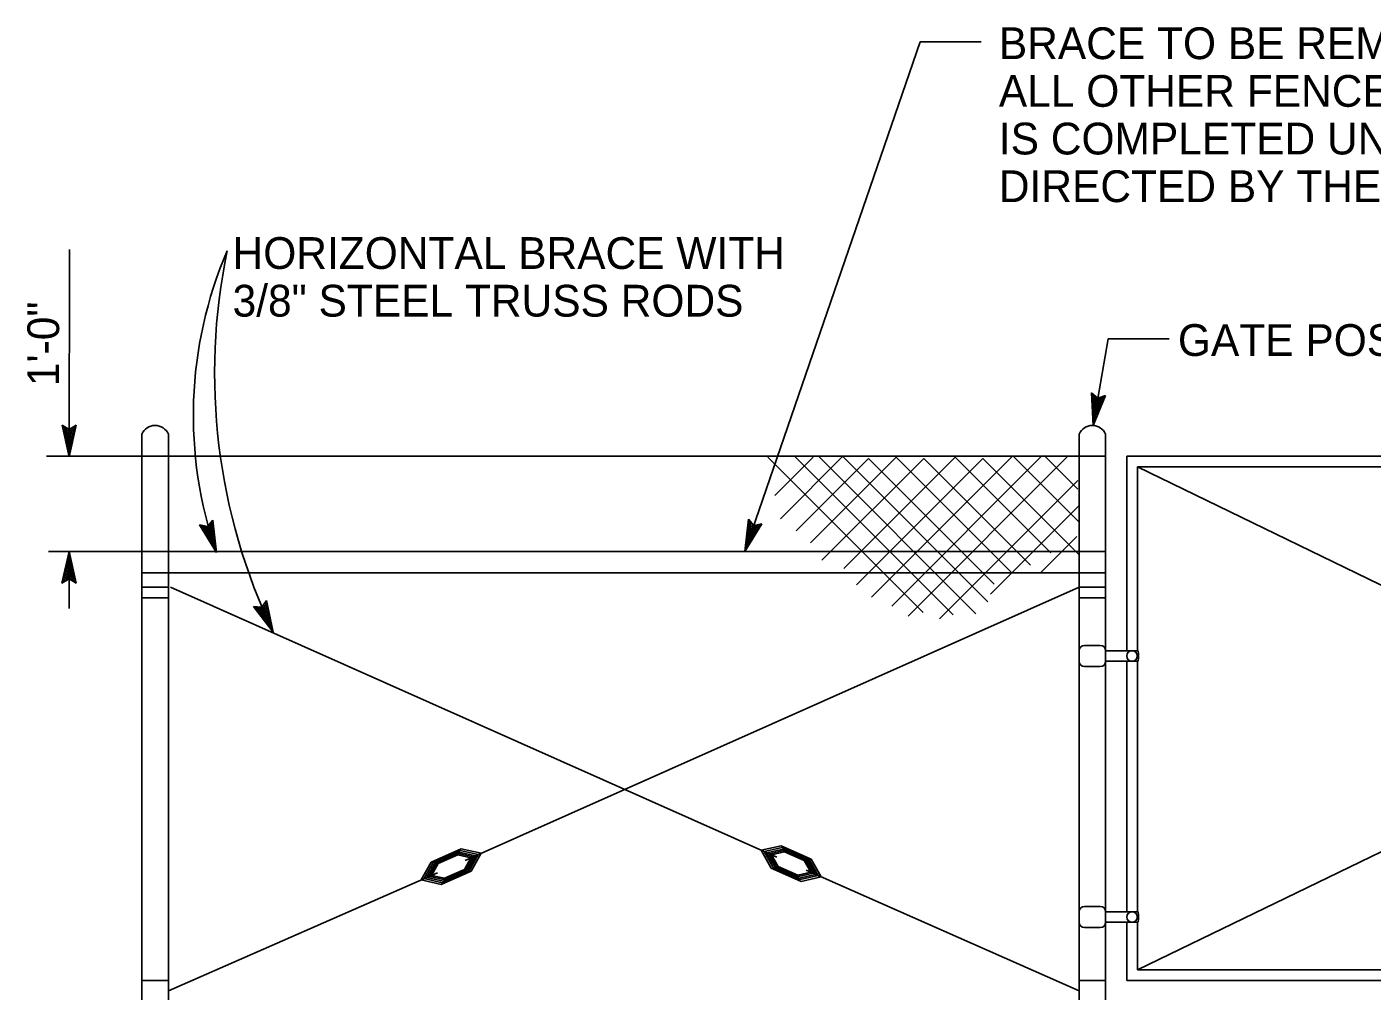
# Model space of a CAD drawing. Extents: x -121875 to -117742, y -103854 to -101122.
# Drawn here: x -121365.7 to -121111.6, y -102377.2 to -102195.2 of the extents above; entities that cross this region are included whole.
import ezdxf

# ---------------------------------------------------------------- set-up
doc = ezdxf.new("R2010")
doc.units = 0
for name, color, linetype in [('G-MARK', 7, 'Continuous'), ('G-TEXT', 7, 'Continuous'), ('Misc CnstDet(22)', 7, 'Continuous'), ('Nongeo Data(60)', 7, 'Continuous')]:
    doc.layers.add(name, color=color, linetype=linetype)

msp = doc.modelspace()

# ---------------------------------------------------------------- linework, layer by layer
at = {"layer": 'G-MARK'}
for p, q in [((-121197, -102197.99), (-121185.5, -102197.99)), ((-121357.66, -102237.2), (-121357.7, -102276.37)), ((-121161.49, -102254.04), (-121149.99, -102254.04)), ((-121164.33, -102270.41), (-121164.62, -102264.27)), ((-121164.62, -102264.27), (-121164.62, -102264.27)), ((-121164.62, -102264.27), (-121163.44, -102265.29)), ((-121161.99, -102264.73), (-121164.33, -102270.41)), ((-121164.1, -102269.04), (-121164.3, -102264.56)), ((-121163.86, -102267.69), (-121163.99, -102264.8)), ((-121163.44, -102265.29), (-121161.99, -102264.73)), ((-121161.99, -102264.73), (-121161.99, -102264.73)), ((-121162.37, -102264.88), (-121164.1, -102269.05)), ((-121162.77, -102265.05), (-121163.86, -102267.69)), ((-121163.62, -102266.33), (-121163.68, -102265.09)), ((-121163.14, -102265.16), (-121163.62, -102266.33)), ((-121164.33, -102270.41), (-121164.33, -102270.41)), ((-121230.1, -102294.24), (-121229.41, -102288.14)), ((-121226.89, -102289.01), (-121230.1, -102294.24)), ((-121229.66, -102292.93), (-121229.15, -102288.48)), ((-121227.29, -102289.09), (-121229.66, -102292.94)), ((-121229.41, -102288.14), (-121229.41, -102288.14)), ((-121229.41, -102288.14), (-121228.41, -102289.33)), ((-121229.2, -102291.63), (-121228.88, -102288.76)), ((-121227.71, -102289.2), (-121229.2, -102291.63)), ((-121228.75, -102290.33), (-121228.61, -102289.1)), ((-121228.09, -102289.25), (-121228.75, -102290.33)), ((-121228.41, -102289.33), (-121226.89, -102289.01)), ((-121226.89, -102289.01), (-121226.89, -102289.01)), ((-121357.72, -102294.19), (-121357.73, -102304.97)), ((-121230.1, -102294.24), (-121230.1, -102294.24))]:
    msp.add_line(p, q, dxfattribs=at)
for points in [[(-121230.1, -102294.24), (-121197, -102197.99), (-121197, -102197.99)], [(-121164.33, -102270.41), (-121161.49, -102254.04)]]:
    msp.add_lwpolyline(points, dxfattribs=at)
for centre, radius, start, end in [((-121255.69, -102268.51), 78.56, 156.7153, 199.2421), ((-121216.67, -102260.54), 113.56, 168.2679, 205.5228)]:
    msp.add_arc(centre, radius, start, end, dxfattribs=at)
at = {"layer": 'G-TEXT'}
for p, q in [((-121357.7, -102276.37), (-121359.02, -102270.37)), ((-121359.02, -102270.37), (-121359.02, -102270.37)), ((-121359.02, -102270.37), (-121357.69, -102271.17)), ((-121357.7, -102274.98), (-121358.67, -102270.61)), ((-121357.69, -102273.61), (-121358.32, -102270.79)), ((-121357.69, -102272.23), (-121357.96, -102271.02)), ((-121356.35, -102270.38), (-121357.7, -102276.37)), ((-121356.71, -102270.59), (-121357.7, -102274.99)), ((-121357.69, -102271.17), (-121356.35, -102270.38)), ((-121357.07, -102270.83), (-121357.69, -102273.61)), ((-121357.42, -102271), (-121357.69, -102272.23)), ((-121356.35, -102270.38), (-121356.35, -102270.38)), ((-121357.7, -102276.37), (-121357.7, -102276.37)), ((-121329.87, -102294.4), (-121333.07, -102289.16)), ((-121333.07, -102289.16), (-121333.07, -102289.16)), ((-121333.07, -102289.16), (-121331.56, -102289.48)), ((-121330.32, -102293.09), (-121332.66, -102289.26)), ((-121330.76, -102291.79), (-121332.27, -102289.32)), ((-121331.21, -102290.48), (-121331.86, -102289.42)), ((-121331.56, -102289.48), (-121330.55, -102288.29)), ((-121331.35, -102289.23), (-121331.21, -102290.48)), ((-121331.08, -102288.95), (-121330.76, -102291.79)), ((-121330.82, -102288.61), (-121330.31, -102293.09)), ((-121330.55, -102288.29), (-121330.55, -102288.29)), ((-121330.55, -102288.29), (-121329.87, -102294.4)), ((-121359.06, -102300.19), (-121357.72, -102294.19)), ((-121357.72, -102294.19), (-121357.72, -102294.19)), ((-121357.72, -102294.19), (-121356.39, -102300.19)), ((-121329.87, -102294.4), (-121329.87, -102294.4)), ((-121358.71, -102299.97), (-121357.72, -102295.57)), ((-121358.35, -102299.74), (-121357.72, -102296.95)), ((-121357.72, -102295.58), (-121356.75, -102299.95)), ((-121357.72, -102296.95), (-121357.1, -102299.78)), ((-121357.72, -102299.39), (-121359.06, -102300.19)), ((-121359.06, -102300.19), (-121359.06, -102300.19)), ((-121358, -102299.56), (-121357.73, -102298.33)), ((-121357.73, -102298.33), (-121357.46, -102299.54)), ((-121356.39, -102300.19), (-121357.72, -102299.39)), ((-121356.39, -102300.19), (-121356.39, -102300.19)), ((-121319.15, -102309.47), (-121322.88, -102304.59)), ((-121322.88, -102304.59), (-121322.88, -102304.59)), ((-121322.88, -102304.59), (-121321.34, -102304.76)), ((-121319.74, -102308.21), (-121322.45, -102304.65)), ((-121320.31, -102306.97), (-121322.06, -102304.67)), ((-121320.89, -102305.71), (-121321.64, -102304.73)), ((-121321.34, -102304.76), (-121320.46, -102303.47)), ((-121321.16, -102304.48), (-121320.89, -102305.71)), ((-121320.92, -102304.18), (-121320.31, -102306.97)), ((-121320.69, -102303.81), (-121319.73, -102308.22)), ((-121320.46, -102303.47), (-121320.46, -102303.47)), ((-121320.46, -102303.47), (-121319.15, -102309.47)), ((-121319.15, -102309.47), (-121319.15, -102309.47))]:
    msp.add_line(p, q, dxfattribs=at)
at = {"layer": 'Nongeo Data(60)'}
for p, q in [((-121343.97, -102426.24), (-121343.97, -102272.05)), ((-121338.97, -102426.24), (-121338.97, -102272.05)), ((-121166.97, -102358.97), (-121166.97, -102272.05)), ((-121161.97, -102358.97), (-121161.97, -102272.05)), ((-121343.8, -102276.24), (-121361.96, -102276.24)), ((-121343.97, -102426.24), (-121343.97, -102276.24)), ((-121161.97, -102276.24), (-121343.8, -102276.24)), ((-121196.43, -102305.72), (-121225.74, -102276.41)), ((-121224.43, -102283.65), (-121217.2, -102276.41)), ((-121223.37, -102288.04), (-121211.5, -102276.17)), ((-121190.73, -102306.2), (-121220.76, -102276.17)), ((-121220.4, -102290.29), (-121206.75, -102276.65)), ((-121217.67, -102292.55), (-121201.53, -102276.41)), ((-121186.46, -102305.96), (-121216.25, -102276.17)), ((-121215.53, -102295.87), (-121196.31, -102276.65)), ((-121184.21, -102303.7), (-121211.74, -102276.17)), ((-121211.38, -102297.41), (-121190.38, -102276.41)), ((-121209.01, -102300.5), (-121185.16, -102276.65)), ((-121183.02, -102300.38), (-121206.75, -102276.65)), ((-121206.16, -102302.87), (-121179.46, -102276.17)), ((-121202.34, -102304.51), (-121174.01, -102276.18)), ((-121179.82, -102298.13), (-121201.53, -102276.41)), ((-121199.28, -102306.43), (-121169.02, -102276.17)), ((-121176.14, -102296.82), (-121196.31, -102276.65)), ((-121172.34, -102294.45), (-121190.38, -102276.41)), ((-121167, -102294.8), (-121185.16, -102276.65)), ((-121167, -102288.63), (-121179.46, -102276.17)), ((-121167.2, -102282.47), (-121173.6, -102276.07)), ((-121157.97, -102312.97), (-121157.97, -102276.24)), ((-120957.97, -102276.24), (-121157.97, -102276.24)), ((-121155.97, -102312.95), (-121155.97, -102278.24)), ((-121155.97, -102278.24), (-121019.1, -102344.59)), ((-120959.97, -102278.24), (-121155.97, -102278.24)), ((-121193.34, -102306.91), (-121167.21, -102280.78)), ((-121183.73, -102302.28), (-121166.96, -102285.51)), ((-121174.12, -102298.13), (-121167.41, -102291.41)), ((-121361.58, -102294.23), (-121340.98, -102294.23)), ((-121161.97, -102294.24), (-121343.97, -102294.24)), ((-121161.97, -102298.24), (-121343.97, -102298.24)), ((-121338.97, -102300.95), (-121343.97, -102300.95)), ((-121338.97, -102302.95), (-121343.97, -102302.95)), ((-121338.57, -102300.95), (-121224.03, -102351.93)), ((-121166.97, -102300.95), (-121282.92, -102352.55)), ((-121161.97, -102300.95), (-121166.97, -102300.95)), ((-121161.97, -102302.95), (-121166.97, -102302.95)), ((-121166.97, -102311.94), (-121166.97, -102309.67)), ((-121161.97, -102311.93), (-121161.97, -102309.67)), ((-121157.97, -102312.95), (-121157.97, -102309.67)), ((-121166.97, -102317.59), (-121166.97, -102311.9)), ((-121166.97, -102314.95), (-121166.97, -102312.95)), ((-121162.97, -102311.95), (-121165.97, -102311.95)), ((-121161.97, -102317.59), (-121161.97, -102311.93)), ((-121155.85, -102312.95), (-121161.97, -102312.95)), ((-121161.97, -102314.95), (-121161.97, -102312.95)), ((-121155.85, -102314.95), (-121161.97, -102314.95)), ((-121157.97, -102358.97), (-121157.97, -102314.81)), ((-121157.97, -102317.59), (-121157.97, -102314.95)), ((-121155.97, -102362.24), (-121155.97, -102314.95)), ((-121162.97, -102315.95), (-121165.97, -102315.95)), ((-121100.56, -102346.39), (-121155.97, -102373.24)), ((-121283.68, -102350.35), (-121289.34, -102352.87)), ((-121283.86, -102350.69), (-121288.96, -102352.96)), ((-121284.03, -102350.99), (-121288.61, -102353.03)), ((-121280.97, -102351.68), (-121284.03, -102350.99)), ((-121280.47, -102351.45), (-121283.86, -102350.69)), ((-121279.91, -102351.2), (-121283.68, -102350.35)), ((-121281.8, -102354.57), (-121279.91, -102351.2)), ((-121227.01, -102350.62), (-121223.24, -102349.77)), ((-121225.12, -102353.99), (-121227.01, -102350.62)), ((-121226.44, -102350.88), (-121223.05, -102350.11)), ((-121224.74, -102353.91), (-121226.44, -102350.88)), ((-121225.93, -102351.11), (-121222.88, -102350.42)), ((-121224.4, -102353.84), (-121225.93, -102351.11)), ((-121225.47, -102351.31), (-121222.72, -102350.69)), ((-121225.06, -102351.5), (-121222.59, -102350.94)), ((-121223.24, -102349.77), (-121217.58, -102352.29)), ((-121223.05, -102350.11), (-121217.95, -102352.38)), ((-121222.88, -102350.42), (-121218.29, -102352.46)), ((-121222.72, -102350.69), (-121218.6, -102352.53)), ((-121222.59, -102350.94), (-121218.87, -102352.59)), ((-121289.34, -102352.87), (-121291.23, -102356.24)), ((-121288.96, -102352.96), (-121290.66, -102355.99)), ((-121288.61, -102353.03), (-121290.15, -102355.76)), ((-121288.3, -102353.1), (-121289.68, -102355.56)), ((-121288.02, -102353.16), (-121289.26, -102355.38)), ((-121284.17, -102351.26), (-121288.3, -102353.1)), ((-121284.31, -102351.51), (-121288.02, -102353.16)), ((-121281.83, -102352.07), (-121284.31, -102351.51)), ((-121281.43, -102351.88), (-121284.17, -102351.26)), ((-121283.07, -102354.28), (-121281.83, -102352.07)), ((-121282.8, -102354.34), (-121281.43, -102351.88)), ((-121282.5, -102354.41), (-121280.97, -102351.68)), ((-121282.17, -102354.49), (-121280.47, -102351.45)), ((-121224.09, -102353.77), (-121225.47, -102351.31)), ((-121223.82, -102353.71), (-121225.06, -102351.5)), ((-121220.1, -102355.36), (-121223.82, -102353.71)), ((-121218.87, -102352.59), (-121217.63, -102354.8)), ((-121218.6, -102352.53), (-121217.22, -102354.99)), ((-121218.29, -102352.46), (-121216.76, -102355.19)), ((-121217.95, -102352.38), (-121216.25, -102355.42)), ((-121217.58, -102352.29), (-121215.69, -102355.67)), ((-121288.13, -102354.87), (-121338.94, -102377.21)), ((-121291.23, -102356.24), (-121287.46, -102357.09)), ((-121290.66, -102355.99), (-121287.27, -102356.76)), ((-121290.15, -102355.76), (-121287.09, -102356.45)), ((-121289.68, -102355.56), (-121286.93, -102356.18)), ((-121289.26, -102355.38), (-121286.79, -102355.93)), ((-121287.46, -102357.09), (-121281.8, -102354.57)), ((-121287.27, -102356.76), (-121282.17, -102354.49)), ((-121287.09, -102356.45), (-121282.5, -102354.41)), ((-121286.93, -102356.18), (-121282.8, -102354.34)), ((-121286.79, -102355.93), (-121283.07, -102354.28)), ((-121219.46, -102356.52), (-121225.12, -102353.99)), ((-121219.65, -102356.18), (-121224.74, -102353.91)), ((-121219.81, -102355.88), (-121224.4, -102353.84)), ((-121219.97, -102355.61), (-121224.09, -102353.77)), ((-121217.63, -102354.8), (-121220.1, -102355.36)), ((-121217.22, -102354.99), (-121219.97, -102355.61)), ((-121216.76, -102355.19), (-121219.81, -102355.88)), ((-121216.25, -102355.42), (-121219.65, -102356.18)), ((-121215.69, -102355.67), (-121219.46, -102356.52)), ((-121218.5, -102354.39), (-121166.95, -102377.17)), ((-121166.97, -102361.24), (-121166.97, -102358.97)), ((-121166.97, -102366.89), (-121166.97, -102358.97)), ((-121166.97, -102366.89), (-121166.97, -102361.19)), ((-121162.97, -102361.24), (-121165.97, -102361.24)), ((-121161.97, -102361.22), (-121161.97, -102358.97)), ((-121161.97, -102366.89), (-121161.97, -102358.97)), ((-121161.97, -102366.89), (-121161.97, -102361.22)), ((-121157.97, -102362.24), (-121157.97, -102358.97)), ((-121157.97, -102362.19), (-121157.97, -102358.97)), ((-121166.97, -102364.24), (-121166.97, -102362.24)), ((-121161.97, -102364.24), (-121161.97, -102362.24)), ((-121155.85, -102362.24), (-121161.86, -102362.24)), ((-121162.97, -102365.24), (-121165.97, -102365.24)), ((-121155.85, -102364.24), (-121161.97, -102364.24)), ((-121157.97, -102366.89), (-121157.97, -102364.24)), ((-121155.97, -102366.89), (-121155.97, -102364.24)), ((-121155.97, -102366.89), (-121155.97, -102364.24)), ((-121166.97, -102426.24), (-121166.97, -102366.89)), ((-121161.97, -102426.24), (-121161.97, -102366.89)), ((-121157.97, -102375.24), (-121157.97, -102366.89)), ((-121155.97, -102373.24), (-121155.97, -102366.89)), ((-120959.97, -102373.24), (-121155.97, -102373.24)), ((-121338.97, -102375.24), (-121343.97, -102375.24)), ((-121161.97, -102375.24), (-121166.97, -102375.24)), ((-120957.97, -102375.24), (-121157.97, -102375.24))]:
    msp.add_line(p, q, dxfattribs=at)
for centre in [(-121156.98, -102313.95), (-121156.97, -102363.24)]:
    msp.add_circle(centre, 1, dxfattribs=at)
for centre, radius, start, end in [((-121341.47, -102273.13), 2.72, 23.2888, 156.7112), ((-121164.47, -102273.13), 2.72, 23.2888, 156.7112), ((-121165.97, -102312.95), 1, 90, 180), ((-121162.97, -102312.95), 1, 0, 90), ((-121165.97, -102314.95), 1, 180, 270), ((-121162.97, -102314.95), 1, 270, 0), ((-121165.97, -102362.24), 1, 90, 180), ((-121162.97, -102362.24), 1, 0, 90), ((-121165.97, -102364.24), 1, 180, 270), ((-121162.97, -102364.24), 1, 270, 0)]:
    msp.add_arc(centre, radius, start, end, dxfattribs=at)
for centre in [(-121155.85, -102313.95), (-121155.85, -102363.24)]:
    msp.add_ellipse(centre, major_axis=(0, -1), ratio=0.098201, start_param=0, end_param=3.141593, dxfattribs=at)

# ---------------------------------------------------------------- texts
at = {"layer": 'Misc CnstDet(22)'}
for s, p in [('BRACE TO BE REMOVED AFTER', (-121182.13, -102201.24)), ('ALL OTHER FENCE CONSTRUCTION', (-121182.13, -102210.24)), ('IS COMPLETED UNLESS OTHERWISE', (-121182.13, -102219.24)), ('DIRECTED BY THE ENGINEER', (-121182.13, -102228.24)), ('HORIZONTAL BRACE WITH', (-121326.84, -102240.86)), ('3/8" STEEL TRUSS RODS', (-121326.84, -102249.86)), ('GATE POST', (-121148.31, -102257.29))]:
    msp.add_text(s, height=6, dxfattribs=at).set_placement(p)
at = {"layer": 'Nongeo Data(60)'}
msp.add_text('1\'-0"', height=6, rotation=90, dxfattribs=at).set_placement((-121359.59, -102262.99))

doc.saveas('drawing.dxf')
